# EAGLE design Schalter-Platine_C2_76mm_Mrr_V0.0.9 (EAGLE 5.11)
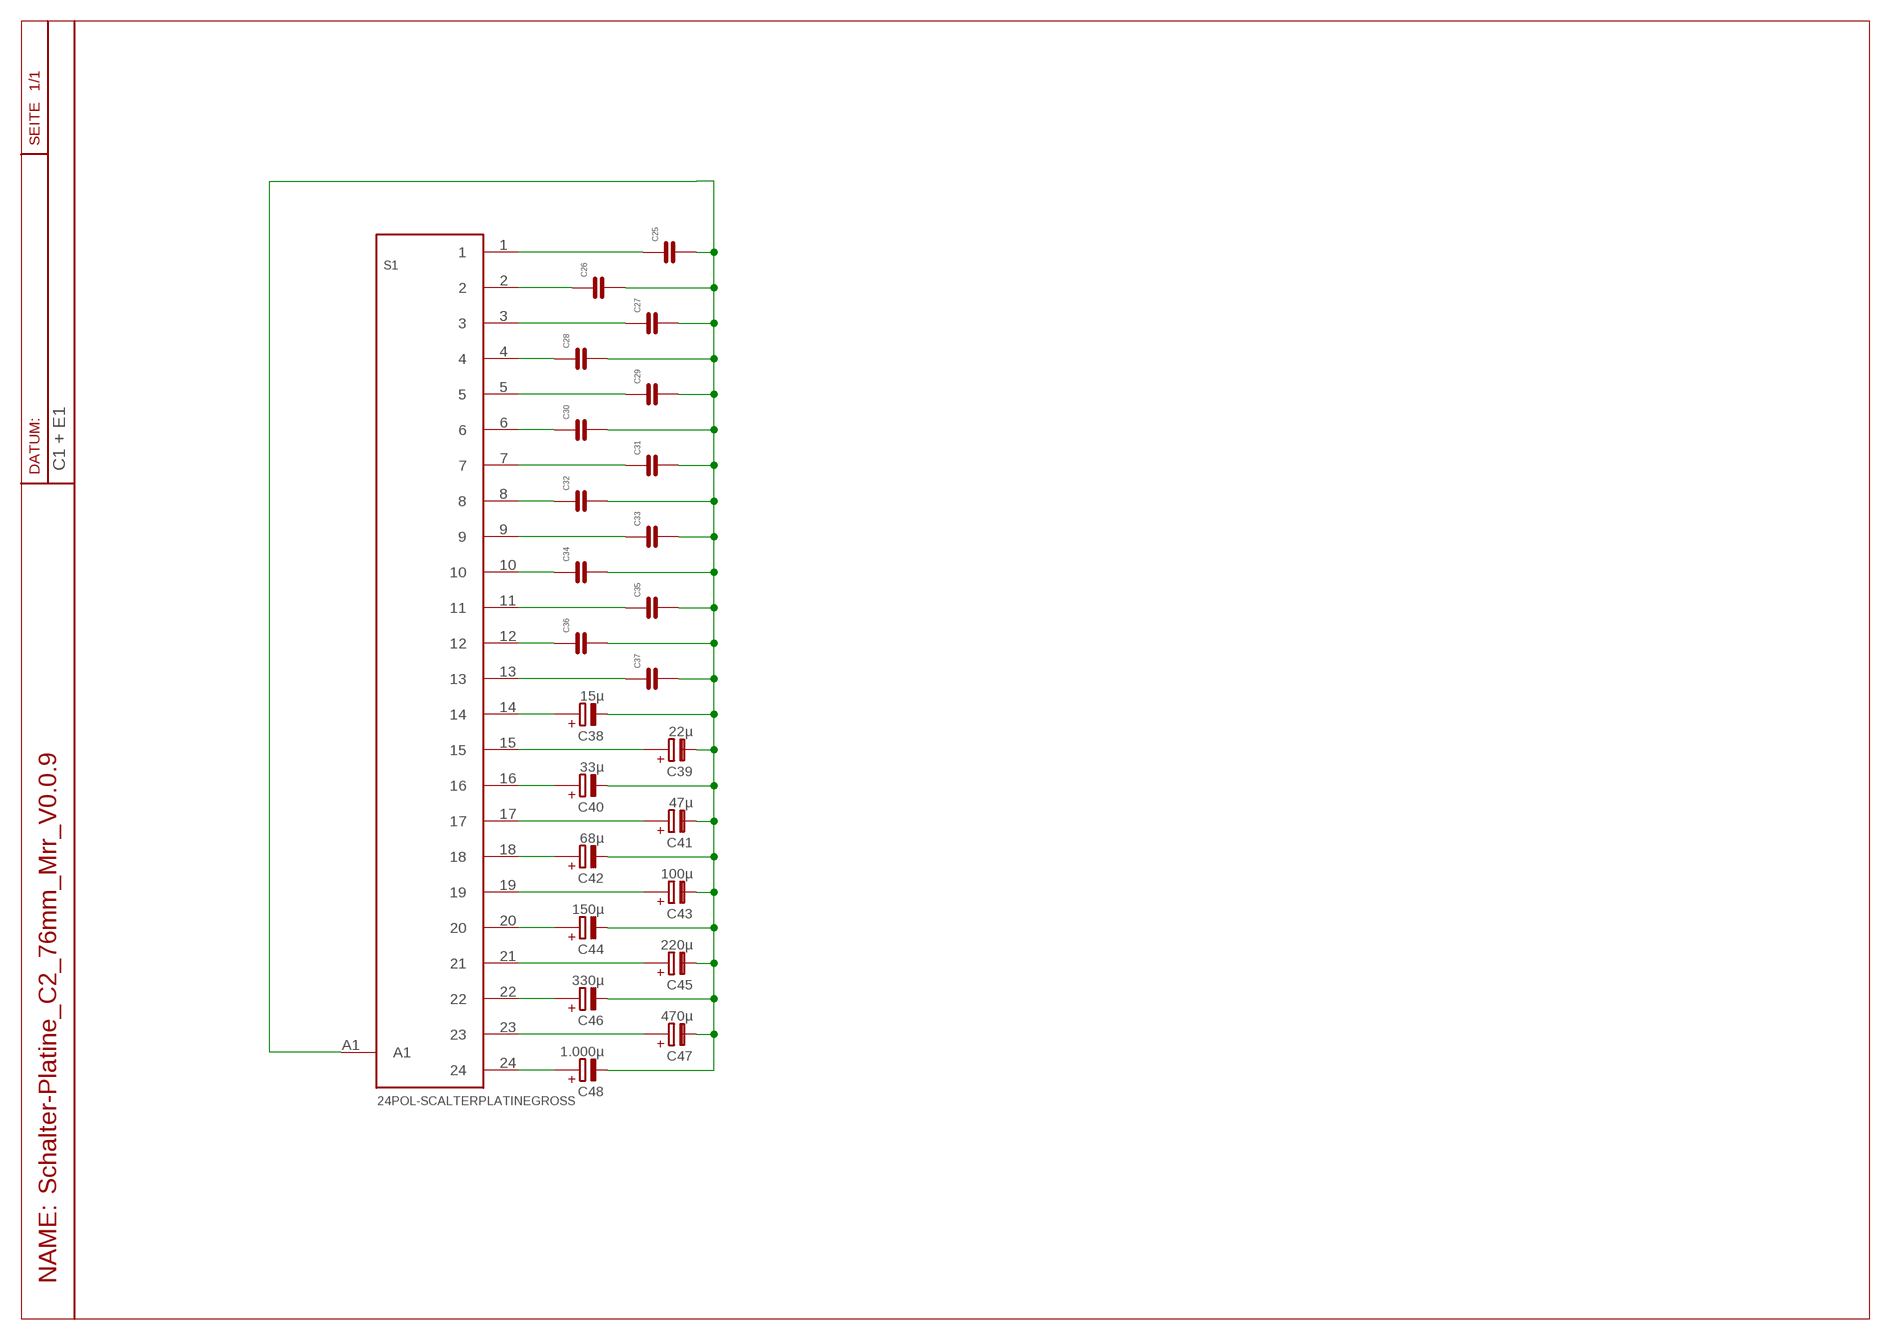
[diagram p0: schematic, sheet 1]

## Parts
C25  C-RM57,2X5  [C5-7,2X5]
C26  C-RM57,2X5,5  [C5-7,2X5,5]
C27  C-RM57,2X7.2  [C5-7,2X7,2]
C28  C-RM57,2/8,5  [C5-7,2X8,5]
C29  C-RM57,2/8,5  [C5-7,2X8,5]
C30  C-RM57,2/8,5  [C5-7,2X8,5]
C31  C-RM57,2X11  [C5-7,2X11]
C32  C-RM57,2X5  [C5-7,2X5]
C33  C-RM57,2X5  [C5-7,2X5]
C34  C-RM57,2X7.2  [C5-7,2X7,2]
C35  C-RM57,2/8,5  [C5-7,2X8,5]
C36  C-RM57,2/8,5  [C5-7,2X8,5]
C37  C-RM57,2X11  [C5-7,2X11]
C38  15µ  E2-5  [E2-5]
C39  22µ  E2,5-6E  [E2,5-6E]
C40  33µ  E2,5-6E  [E2,5-6E]
C41  47µ  E3,5-8E  [E3,5-8E]
C42  68µ  E3,5-8E  [E3,5-8E]
C43  100µ  E5-10,5  [E5-10,5]
C44  150µ  E5-10,5  [E5-10,5]
C45  220µ  E5-10,5  [E5-10,5]
C46  330µ  E5-13  [E5-13]
C47  470µ  E5-13  [E5-13]
C48  1.000µ  E7,5-16  [E7,5-16]
S1  24POL-SCALTERPLATINEGROSS  [DREHSCHALTER-GROSS]

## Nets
N$1: C25.1 S1.1
N$2: C26.1 S1.2
N$3: C27.1 S1.3
N$4: C28.1 S1.4
N$5: C29.1 S1.5
N$6: C30.1 S1.6
N$7: C31.1 S1.7
N$8: C32.1 S1.8
N$9: C33.1 S1.9
N$10: C34.1 S1.10
N$11: C35.1 S1.11
N$12: C36.1 S1.12
N$13: C37.1 S1.13
N$14: C38.+ S1.14
N$15: C39.+ S1.15
N$16: C40.+ S1.16
N$17: C41.+ S1.17
N$18: C42.+ S1.18
N$19: C43.+ S1.19
N$20: C44.+ S1.20
N$21: C45.+ S1.21
N$22: C46.+ S1.22
N$23: C47.+ S1.23
N$24: C48.+ S1.24
N$25: C25.2 C26.2 C27.2 C28.2 C29.2 C30.2 C31.2 C32.2 C33.2 C34.2 C35.2 C36.2 C37.2 C38.- C39.- C40.- C41.- C42.- C43.- C44.- C45.- C46.- C47.- C48.- S1.A1

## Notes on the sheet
- C1 + E1

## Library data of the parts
C25-C37 = RLC-BOX:C-RM5
C38 = Elkos:E2-5
C39 C40 = Elkos:E2,5-6E
C41 C42 = Elkos:E3,5-8E
C43-C45 = Elkos:E5-10,5
C46 C47 = Elkos:E5-13
C48 = Elkos:E7,5-16
S1 = RLC-BOX:24POL-SCALTERPLATINE

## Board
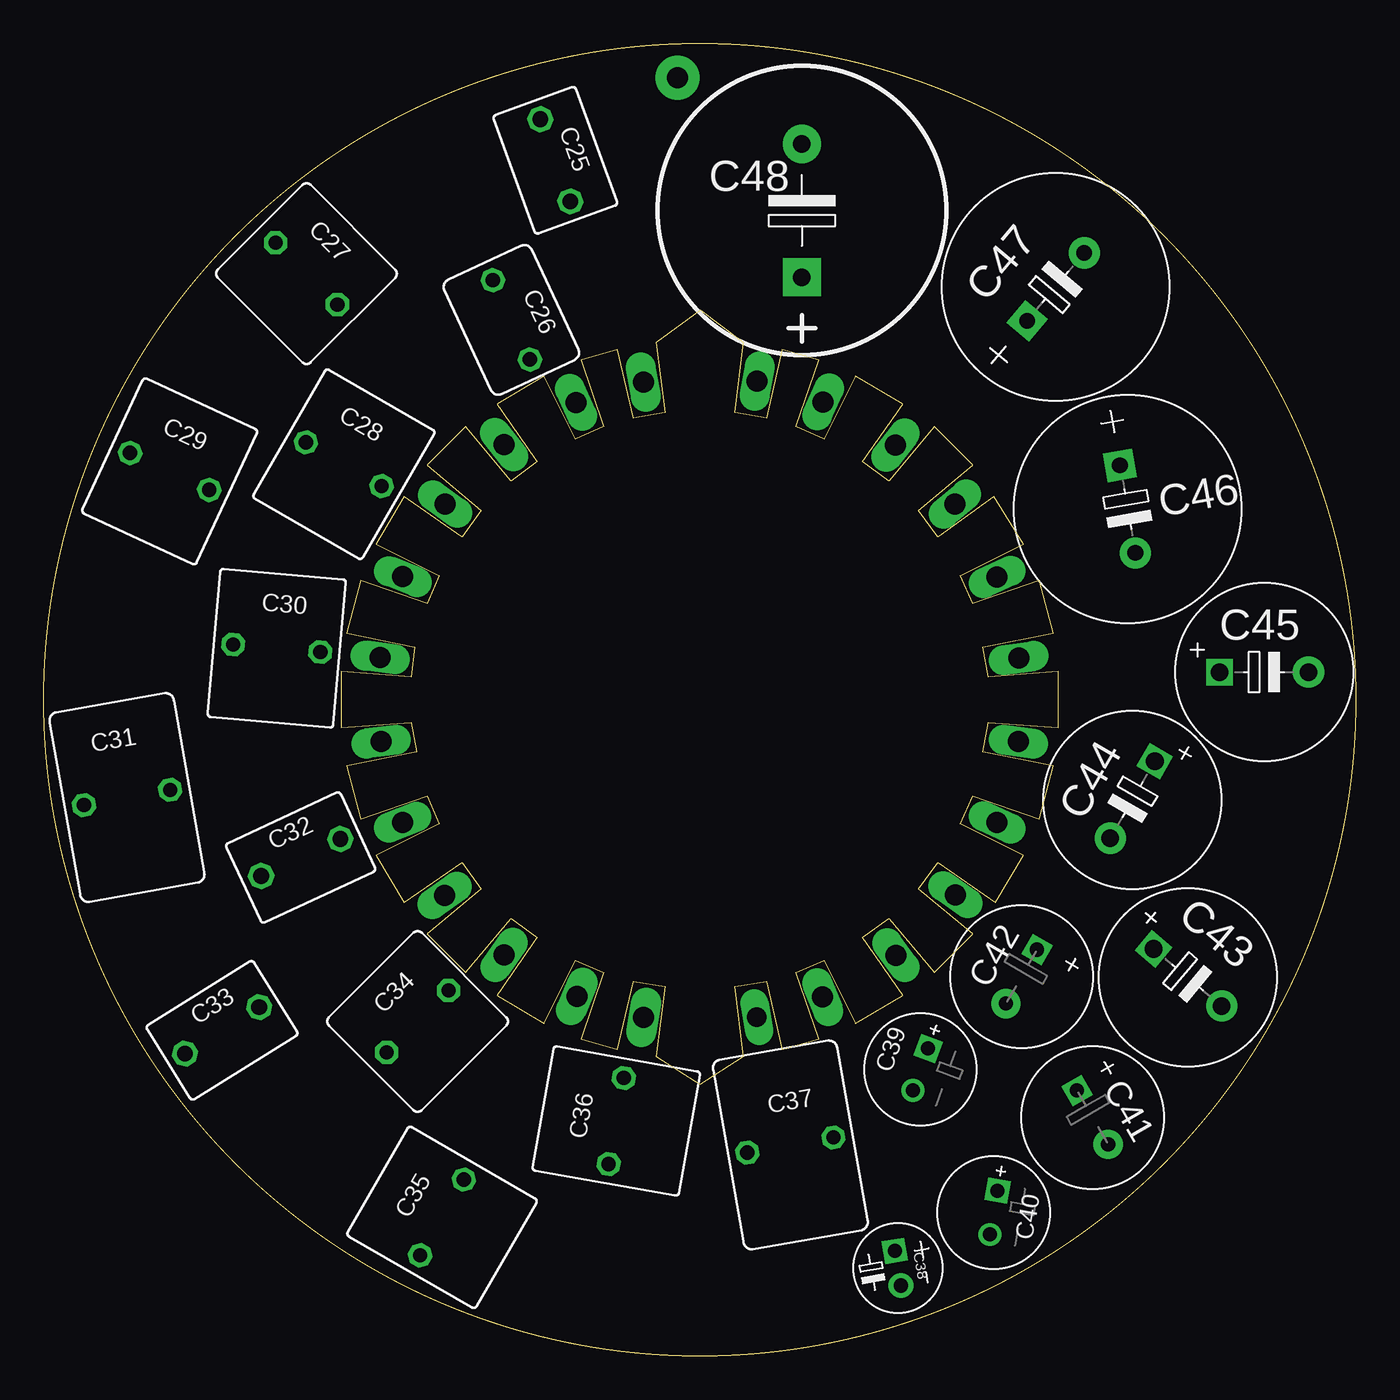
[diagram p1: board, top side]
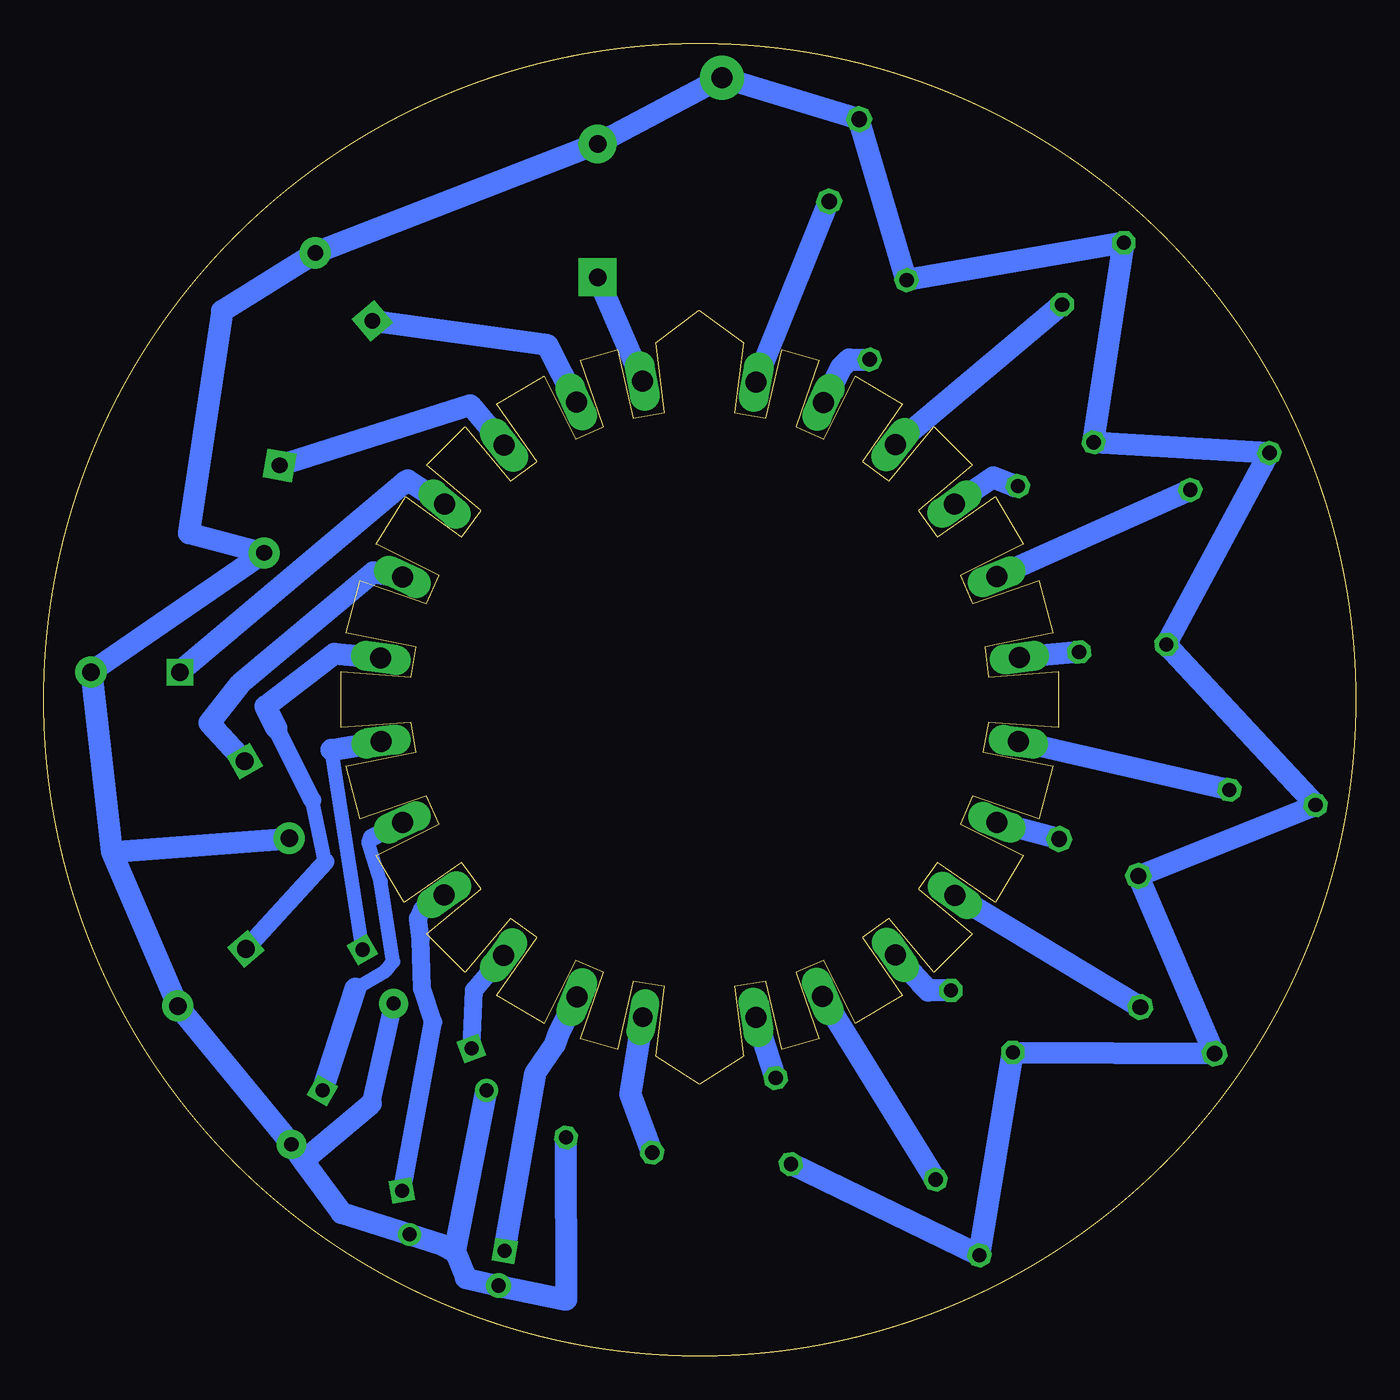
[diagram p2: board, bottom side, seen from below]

Size 75 x 75 mm. Coordinates in mm from the lower left corner, seen from the top.
Outline: circle at 37.5,37.5 radius 37.5
Copper layers (1*16): Top 0.035mm / dielectric 1.5mm / Bottom 0.035mm
Design rules "PCBWay *": minimum track width 8mil, minimum drill 0.3mm, track to track 6mil, track to pad 6mil, pad to pad 6mil, via to via 6mil, smd to smd 6mil, copper to edge 40mil, drill to drill 8mil, minimum pad ring 10mil, minimum via ring 8mil, stop-mask expansion 4mil, vias tented up to drill 0mil, thermal gap 20mil

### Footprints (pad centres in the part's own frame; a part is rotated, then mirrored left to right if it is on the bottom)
C5-7,2X5 = drill 0.9 octagon: 1 -2.5,0; 2 2.5,0
C5-7,2X5,5 = drill 0.813 octagon: 1 -2.5,0; 2 2.5,0
C5-7,2X7,2 = drill 0.813 octagon: 1 -2.5,0; 2 2.5,0
C5-7,2X8,5 = drill 0.813 octagon: 1 -2.5,0; 2 2.5,0
C5-7,2X11 = drill 0.813 octagon: 1 -2.5,0; 2 2.5,0
E2-5 = drill 0.8 square: + -1,0 | drill 0.813 pad 1.422 round: - 1.016,0
E2,5-6E = drill 0.8 square: + 0,0 | drill 0.8 round: - 2.54,0
E3,5-8E = drill 0.813 square: + -1.778,0 | drill 0.813 pad 1.676 round: - 1.778,0
E5-10,5 = drill 1.016 square: + -2.54,0 | drill 1 pad 1.778 round: - 2.54,0
E5-13 = drill 0.9 pad 1.676 square: + -2.54,0 | drill 0.9 pad 1.778 round: - 2.54,0
E7,5-16 = drill 1 pad 2.184 square: + -3.81,0 | drill 1 pad 2.184 round: - 3.81,0
DREHSCHALTER-GROSS = drill 1.2 pad 1.6 long: 1 3.228,18.163; 2 7.064,16.998; 3 11.181,14.582; 4 14.562,11.184; 5 16.972,7.033; 6 18.265,2.413; 7 18.212,-2.398; 8 16.982,-7.008; 9 14.582,-11.189; 10 11.189,-14.575; 11 7.026,-16.97; 12 3.208,-18.151; 14 -7.025,-16.995; 15 -11.209,-14.607; 16 -14.62,-11.143; 17 -16.99,-7.01; 18 -18.219,-2.395; 19 -18.23,2.39; 20 -16.99,7.023; 21 -14.585,11.181; 22 -11.196,14.554; 23 -7.056,17.026; 24 -3.282,18.225 | drill 1.1 pad 1.6 long: 13 -3.256,-18.141 | drill 1.2 pad 2.5 round: A1 1.27,35.56

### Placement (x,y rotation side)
C25  29.24,68.34 110 top
C26  26.73,59.22 115 top
C27  15.02,61.86 135 top
C28  17.15,50.96 150 top
C29  7.2,50.56 155 top
C30  13.32,40.45 175 top
C31  4.76,31.91 190 top
C32  14.69,28.48 205 top
C33  10.19,18.6 212 top
C34  21.37,19.11 225 top
C35  22.77,7.91 240 top
C36  32.72,13.42 260 top
C37  42.68,12.05 10 top
C38  48.83,5.01 280 top
C39  50.56,17.56 250 top
C40  54.52,9.43 260 top
C41  59.95,13.62 300 top
C42  55.89,21.68 240 top
C43  65.39,21.62 320 top
C44  62.24,31.78 240 top
C45  69.76,39.07 0 top
C46  61.96,48.4 280 top
C47  57.85,61.1 50 top
C48  43.34,65.47 90 top
S1  37.5,37.5 0 bottom

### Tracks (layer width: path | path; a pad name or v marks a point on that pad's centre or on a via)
N$1
  Bottom 1.27: S1.1 C25.1
N$2
  Bottom 1.27: S1.2 29.37,56.55 28.97,56.95 C26.1
N$3
  Bottom 1.27: C27.1 S1.3
N$4
  Bottom 1.27: C28.1 19.49,49.71 20.74,50.2 S1.4
N$5
  Bottom 1.27: C29.1 S1.5
N$6
  Bottom 1.27: C30.1 S1.6
N$7
  Bottom 1.27: C31.1 S1.7
N$8
  Bottom 1.27: C32.1 S1.8
N$9
  Bottom 1.27: C33.1 S1.9
N$10
  Bottom 1.27: C34.1 24.43,20.88 24.8,21.24 S1.10
N$11
  Bottom 1.27: C35.1 S1.11
N$12
  Bottom 1.27: C36.1 S1.12
N$13
  Bottom 1.27: C37.1 41.46,14.94 S1.13
N$14
  Bottom 1.27: S1.14 45.53,18.5 45.78,17.79 46.9,16.16 C38.+
N$15
  Bottom 1.016: S1.15 50.4,20.89 C39.+
N$16
  Bottom 1.016: S1.16 53.38,25.51 53.6,25 53.45,23.83 53.38,20.99 52.74,19.08 C40.+
N$17
  Bottom 0.813: 57.18,20.99 55.46,22.01 55.03,22.54 55.74,27.09 56.45,29.37 56.24,29.6
  Bottom 1.016: S1.17 56.24,29.6
  Bottom 1.27: C41.+ 57.18,20.99
N$18
  Bottom 0.813: C42.+ 58.56,34.63
  Bottom 1.27: 58.56,34.63 S1.18
N$19
  Bottom 0.813: 58.91,28.23 59.65,31.76
  Bottom 1.016: C43.+ 58.91,28.23 | 59.65,31.76 61.71,35.87
  Bottom 1.27: 61.71,35.87 62.32,37.12 58.38,40.14 S1.19
N$20
  Bottom 1.27: S1.20 56.14,44.79 63.76,38.41 65.54,36.18 C44.+
N$21
  Bottom 1.27: S1.21 54.19,50.05 C45.+
N$22
  Bottom 1.27: S1.22 50.61,54.34 C46.+
N$23
  Bottom 1.27: S1.23 46.19,57.77 C47.+
N$24
  Bottom 1.27: S1.24 C48.+
N$25
  Bottom 1.016: 56.3,14.41 C42.-
  Bottom 1.27: 71.1,28.81 C44.- | 71.1,28.81 C45.- C46.- 66.71,47.02 64.81,59.73 C47.- C48.- S1.A1 C25.2 C26.2 C27.2 C28.2 C29.2 C30.2 C31.2 C32.2 C33.2 C34.2 C35.2 C36.2 | 71.1,28.81 C43.- C41.- 60.16,11.15 | 60.16,11.15 57.97,8.16 C40.- 52.21,6.33 51.49,5.98 | 51.49,5.98 50.86,4.43 C38.- 45.12,3.21 C37.2 | 51.49,5.98 C39.- | 60.16,11.15 56.3,14.41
